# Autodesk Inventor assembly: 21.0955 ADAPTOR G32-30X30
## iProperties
Created: 2012-10
Part Number: 21.0955 ADAPTOR G32-30X30
Document SubType Name: Assembly
Designer: Administrator
Author: Administrator
